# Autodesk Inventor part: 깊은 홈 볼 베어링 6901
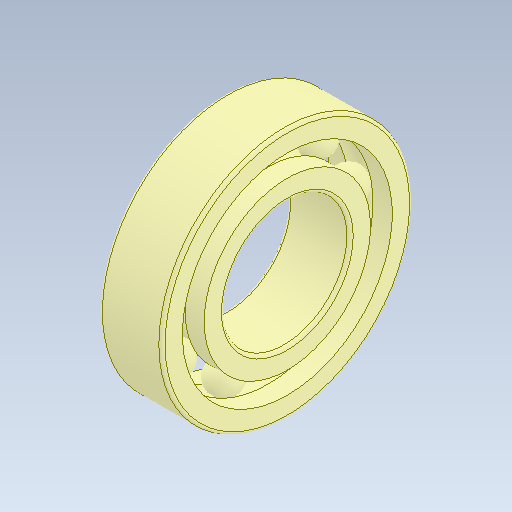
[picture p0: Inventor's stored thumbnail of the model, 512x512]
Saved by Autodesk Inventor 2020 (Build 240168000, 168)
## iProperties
Created: 2024-07
Part Number: 깊은 홈 볼 베어링 6901
Material: 강철, 연강
Description: 깊은 그루브 볼 베어링
Document SubType Name: Modeling
Designer: oem
Density: 7.85 g/cm^3
Appearance: 기본값
Mass: 10.7732 g
Surface Area: 20.7908 cm^2
Volume: 1.37239 cm^3
Sending System: Autodesk Inventor 2025
Preprocessor: ST-DEVELOPER v20
Author: jhkim
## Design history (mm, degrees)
feature "Solid1"
feature "Solid1:1"
feature "Solid1:2"
feature "Solid1:3"
feature "Solid1:4"
feature "Solid1:5"
feature "Solid1:6"
feature "Solid1:7"
feature "Solid1:8"
feature "Solid1:9"
feature "Solid1:10"
node "솔리드1"
node "솔리드2"
node "솔리드3"
node "솔리드4"
node "솔리드5"
node "솔리드6"
node "솔리드7"
node "솔리드8"
node "솔리드9"
node "솔리드10"
node "솔리드11"
